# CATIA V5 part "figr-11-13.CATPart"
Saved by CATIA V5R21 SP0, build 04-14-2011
Part number: Part1
Bounding box of the stored display mesh (mm): x -10 to 5, y -10.258 to 7.91, z -1.915 to 2.054
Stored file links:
  D:\CATIA V5R21 E-RESOURCES\CATIA-V5R21\catia-v5r21-prt\c11-catia-v5r21-prt\c11-catia-v5r21-figr-11-13.CATPart
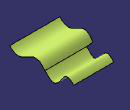
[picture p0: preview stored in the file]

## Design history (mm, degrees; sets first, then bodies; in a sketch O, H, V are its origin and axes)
Set1
  Sketch1 on yz-plane, origin (0, 0, 0), H (0, 1, 0), V (0, 0, 1)
    spline S1 through (-0.358, 0) (-3.1664, 2.0538) (-6.7822, 0.4079) (-10.2576, 1.6423)
    point P1 (-0.358, 0)
    coincidence: P1 H
  Extrude1: Element1 Sketch1, Lim1 5, Lim2 10, Direction yz-plane
  Sketch2 on yz-plane, origin (0, 0, 0), H (0, 1, 0), V (0, 0, 1)
    spline S1 through (0, 0) (3.5471, -1.4404) (5.7957, 1.2855) (7.9098, 0)
    point P1 (0, 0)
    point P2 (7.9098, 0)
    coincidence: P1 O, P2 H
  Extrude2: Element1 Sketch2, Lim1 4, Lim2 8, Direction yz-plane
  Healing1: BodyToHeal (Extrude2; Extrude1), TangencyAngle 0.5, SharpnessAngle 0.5
Body1 (main body)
